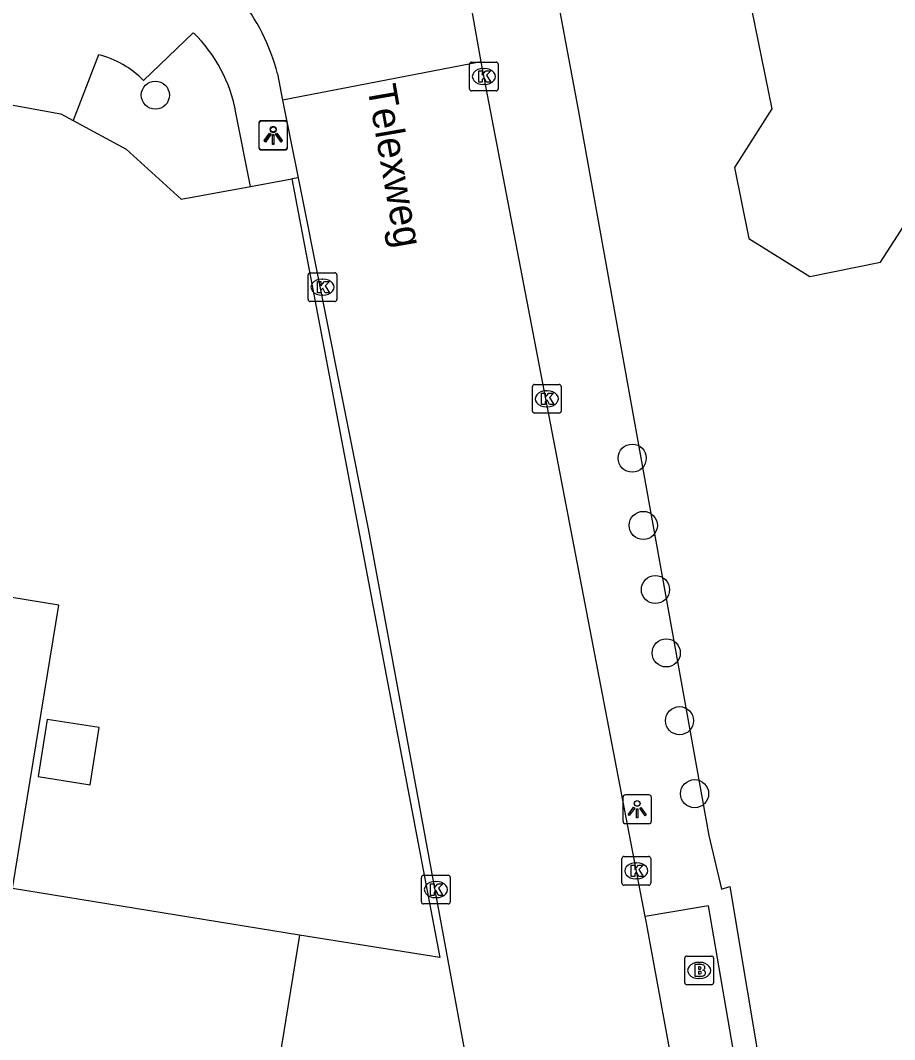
# Model space of a CAD drawing. Extents: x 162990 to 165007, y 383433 to 384336.
# Drawn here: x 163392.98 to 163423.35, y 383982.25 to 384017.67 of the extents above; entities that cross this region are included whole.
import ezdxf

# ---------------------------------------------------------------- set-up
doc = ezdxf.new("R2010")
doc.units = 0
for name, color, linetype in [('IMGEO_Boom', 7, 'Continuous'), ('IMGEO_Brandkraan', 7, 'Continuous'), ('IMGEO_Groenvoorziening', 7, 'Continuous'), ('IMGEO_Hek', 7, 'Continuous'), ('IMGEO_Kolk', 7, 'Continuous'), ('IMGEO_Lage_trafo', 7, 'Continuous'), ('IMGEO_Lichtpunt', 7, 'Continuous'), ('IMGEO_Openbare_ruimte_label', 7, 'Continuous'), ('IMGEO_Pand', 7, 'Continuous'), ('IMGEO_Rijbaan_lokaal_open', 7, 'Continuous'), ('IMGEO_Voetpad_open', 7, 'Continuous')]:
    doc.layers.add(name, color=color, linetype=linetype)

msp = doc.modelspace()

# ---------------------------------------------------------------- linework, layer by layer
at = {"layer": 'IMGEO_Boom'}
for centre in [(163397.667, 384015.068), (163414.235, 384002.456), (163414.62, 384000.118), (163415.043, 383997.891), (163415.418, 383995.69), (163415.879, 383993.335), (163416.403, 383990.798)]:
    msp.add_circle(centre, 0.489, dxfattribs=at)
at = {"layer": 'IMGEO_Brandkraan'}
for p, q in [((163416.137, 383985.158), (163416.989, 383985.158)), ((163416.062, 383984.232), (163416.062, 383985.084)), ((163416.55, 383984.938), (163416.575, 383984.938)), ((163417.063, 383985.084), (163417.063, 383984.232)), ((163416.989, 383984.158), (163416.137, 383984.158)), ((163416.573, 383984.378), (163416.548, 383984.378))]:
    msp.add_line(p, q, dxfattribs=at)
for points in [[(163416.137, 383985.158), (163416.989, 383985.158)], [(163416.062, 383984.232), (163416.062, 383985.084)], [(163416.41, 383984.858), (163416.41, 383984.458), (163416.623, 383984.458)], [(163416.641, 383984.858), (163416.41, 383984.858)], [(163416.589, 383984.777), (163416.535, 383984.777), (163416.535, 383984.701)], [(163417.063, 383985.084), (163417.063, 383984.232)], [(163416.535, 383984.701), (163416.588, 383984.701)], [(163416.597, 383984.625), (163416.535, 383984.625), (163416.535, 383984.544)], [(163416.535, 383984.544), (163416.597, 383984.544)], [(163416.989, 383984.158), (163416.137, 383984.158)]]:
    msp.add_lwpolyline(points, dxfattribs=at)
for centre, radius, start, end in [((163416.139, 383985.082), 0.0765, 91.552, 178.448), ((163416.139, 383985.082), 0.0765, 91.552, 178.448), ((163416.987, 383985.082), 0.0765, 1.552, 88.448), ((163416.987, 383985.082), 0.0765, 1.552, 88.448), ((163416.59, 383984.739), 0.0379, 267.8285, 90.9355), ((163416.645, 383984.713), 0.145, 59.4692, 91.5367), ((163416.67, 383984.76), 0.0922, 285.5137, 58.1501), ((163416.598, 383984.584), 0.0404, 269.8759, 90.5077), ((163416.629, 383984.709), 0.251, 268.6676, 293.5347), ((163416.675, 383984.568), 0.105, 301.3115, 78.989), ((163416.139, 383984.234), 0.0765, 181.552, 268.448), ((163416.139, 383984.234), 0.0765, 181.552, 268.448), ((163416.987, 383984.234), 0.0765, 271.552, 358.448), ((163416.987, 383984.234), 0.0765, 271.552, 358.448)]:
    msp.add_arc(centre, radius, start, end, dxfattribs=at)
for centre, major_axis, ratio, start_param, end_param in [((163416.549, 383984.658), (-0.387, 0.002), 0.722429, 4.712389, 7.853982), ((163416.574, 383984.658), (-0.39, 0.002), 0.717154, 1.570796, 4.712389)]:
    msp.add_ellipse(centre, major_axis=major_axis, ratio=ratio, start_param=start_param, end_param=end_param, dxfattribs=at)
at = {"layer": 'IMGEO_Groenvoorziening'}
msp.add_lwpolyline([(163394.812, 384014.184), (163396.652, 384013.186), (163398.562, 384011.459), (163400.972, 384011.896)], dxfattribs=at)
at = {"layer": 'IMGEO_Hek'}
for points in [[(163359.977, 384000.25), (163372.649, 384005.933), (163381.975, 384010.322), (163389.663, 384014.151), (163392.136, 384014.826), (163394.378, 384014.419), (163394.812, 384014.184)], [(163394.812, 384014.184), (163396.652, 384013.186), (163398.562, 384011.459), (163400.972, 384011.896)], [(163400.972, 384011.896), (163402.405, 384012.156)], [(163402.405, 384012.156), (163407.549, 383985.103), (163402.681, 383985.882)], [(163417.627, 383987.578), (163420.06, 383973.028)]]:
    msp.add_lwpolyline(points, dxfattribs=at)
at = {"layer": 'IMGEO_Kolk'}
for p, q in [((163408.58, 384015.29), (163408.58, 384016.142)), ((163408.655, 384016.216), (163409.507, 384016.216)), ((163409.068, 384015.996), (163409.093, 384015.996)), ((163409.581, 384016.142), (163409.581, 384015.29)), ((163409.507, 384015.216), (163408.655, 384015.216)), ((163409.091, 384015.436), (163409.066, 384015.436)), ((163403.05, 384008.896), (163403.902, 384008.896)), ((163402.975, 384007.97), (163402.975, 384008.822)), ((163403.463, 384008.676), (163403.488, 384008.676)), ((163403.976, 384008.822), (163403.976, 384007.97)), ((163403.902, 384007.896), (163403.05, 384007.896)), ((163403.486, 384008.116), (163403.461, 384008.116)), ((163410.768, 384004.093), (163410.768, 384004.945)), ((163410.843, 384005.019), (163411.695, 384005.019)), ((163411.769, 384004.945), (163411.769, 384004.093)), ((163411.256, 384004.799), (163411.281, 384004.799)), ((163411.279, 384004.239), (163411.254, 384004.239)), ((163411.695, 384004.019), (163410.843, 384004.019)), ((163413.877, 383987.693), (163413.877, 383988.545)), ((163413.952, 383988.619), (163414.804, 383988.619)), ((163414.365, 383988.399), (163414.39, 383988.399)), ((163414.878, 383988.545), (163414.878, 383987.693)), ((163406.987, 383987.966), (163407.839, 383987.966)), ((163406.912, 383987.04), (163406.912, 383987.892)), ((163407.4, 383987.746), (163407.425, 383987.746)), ((163407.913, 383987.892), (163407.913, 383987.04)), ((163414.804, 383987.619), (163413.952, 383987.619)), ((163414.388, 383987.839), (163414.363, 383987.839)), ((163407.839, 383986.966), (163406.987, 383986.966)), ((163407.423, 383987.186), (163407.398, 383987.186))]:
    msp.add_line(p, q, dxfattribs=at)
for points in [[(163408.58, 384015.29), (163408.58, 384016.142)], [(163408.655, 384016.216), (163409.507, 384016.216)], [(163409.581, 384016.142), (163409.581, 384015.29)], [(163408.901, 384015.916), (163409.024, 384015.916), (163409.024, 384015.765), (163409.154, 384015.916), (163409.318, 384015.916), (163409.172, 384015.765), (163409.325, 384015.516), (163409.173, 384015.516), (163409.088, 384015.68), (163409.024, 384015.613), (163409.024, 384015.516), (163408.901, 384015.516), (163408.901, 384015.916)], [(163409.507, 384015.216), (163408.655, 384015.216)], [(163403.05, 384008.896), (163403.902, 384008.896)], [(163402.975, 384007.97), (163402.975, 384008.822)], [(163403.296, 384008.596), (163403.419, 384008.596), (163403.419, 384008.445), (163403.549, 384008.596), (163403.713, 384008.596), (163403.567, 384008.445), (163403.72, 384008.196), (163403.568, 384008.196), (163403.483, 384008.36), (163403.419, 384008.293), (163403.419, 384008.196), (163403.296, 384008.196), (163403.296, 384008.596)], [(163403.976, 384008.822), (163403.976, 384007.97)], [(163403.902, 384007.896), (163403.05, 384007.896)], [(163410.768, 384004.093), (163410.768, 384004.945)], [(163410.843, 384005.019), (163411.695, 384005.019)], [(163411.769, 384004.945), (163411.769, 384004.093)], [(163411.089, 384004.719), (163411.212, 384004.719), (163411.212, 384004.568), (163411.342, 384004.719), (163411.506, 384004.719), (163411.36, 384004.568), (163411.513, 384004.319), (163411.361, 384004.319), (163411.276, 384004.483), (163411.212, 384004.416), (163411.212, 384004.319), (163411.089, 384004.319), (163411.089, 384004.719)], [(163411.695, 384004.019), (163410.843, 384004.019)], [(163413.877, 383987.693), (163413.877, 383988.545)], [(163413.952, 383988.619), (163414.804, 383988.619)], [(163414.198, 383988.319), (163414.321, 383988.319), (163414.321, 383988.168), (163414.451, 383988.319), (163414.615, 383988.319), (163414.469, 383988.168), (163414.622, 383987.919), (163414.47, 383987.919), (163414.385, 383988.083), (163414.321, 383988.016), (163414.321, 383987.919), (163414.198, 383987.919), (163414.198, 383988.319)], [(163414.878, 383988.545), (163414.878, 383987.693)], [(163406.987, 383987.966), (163407.839, 383987.966)], [(163406.912, 383987.04), (163406.912, 383987.892)], [(163407.233, 383987.666), (163407.356, 383987.666), (163407.356, 383987.515), (163407.486, 383987.666), (163407.65, 383987.666), (163407.504, 383987.515), (163407.657, 383987.266), (163407.505, 383987.266), (163407.42, 383987.43), (163407.356, 383987.363), (163407.356, 383987.266), (163407.233, 383987.266), (163407.233, 383987.666)], [(163407.913, 383987.892), (163407.913, 383987.04)], [(163414.804, 383987.619), (163413.952, 383987.619)], [(163407.839, 383986.966), (163406.987, 383986.966)]]:
    msp.add_lwpolyline(points, dxfattribs=at)
for centre, start, end in [((163408.657, 384016.14), 91.552, 178.448), ((163408.657, 384016.14), 91.552, 178.448), ((163409.505, 384016.14), 1.552, 88.448), ((163409.505, 384016.14), 1.552, 88.448), ((163408.657, 384015.292), 181.552, 268.448), ((163408.657, 384015.292), 181.552, 268.448), ((163409.505, 384015.292), 271.552, 358.448), ((163409.505, 384015.292), 271.552, 358.448), ((163403.052, 384008.82), 91.552, 178.448), ((163403.052, 384008.82), 91.552, 178.448), ((163403.9, 384008.82), 1.552, 88.448), ((163403.9, 384008.82), 1.552, 88.448), ((163403.052, 384007.972), 181.552, 268.448), ((163403.052, 384007.972), 181.552, 268.448), ((163403.9, 384007.972), 271.552, 358.448), ((163403.9, 384007.972), 271.552, 358.448), ((163410.845, 384004.943), 91.552, 178.448), ((163410.845, 384004.943), 91.552, 178.448), ((163411.693, 384004.943), 1.552, 88.448), ((163411.693, 384004.943), 1.552, 88.448), ((163410.845, 384004.095), 181.552, 268.448), ((163410.845, 384004.095), 181.552, 268.448), ((163411.693, 384004.095), 271.552, 358.448), ((163411.693, 384004.095), 271.552, 358.448), ((163413.954, 383988.543), 91.552, 178.448), ((163413.954, 383988.543), 91.552, 178.448), ((163414.802, 383988.543), 1.552, 88.448), ((163414.802, 383988.543), 1.552, 88.448), ((163406.989, 383987.89), 91.552, 178.448), ((163406.989, 383987.89), 91.552, 178.448), ((163407.837, 383987.89), 1.552, 88.448), ((163407.837, 383987.89), 1.552, 88.448), ((163413.954, 383987.695), 181.552, 268.448), ((163413.954, 383987.695), 181.552, 268.448), ((163414.802, 383987.695), 271.552, 358.448), ((163414.802, 383987.695), 271.552, 358.448), ((163406.989, 383987.042), 181.552, 268.448), ((163406.989, 383987.042), 181.552, 268.448), ((163407.837, 383987.042), 271.552, 358.448), ((163407.837, 383987.042), 271.552, 358.448)]:
    msp.add_arc(centre, 0.0765, start, end, dxfattribs=at)
for centre, major_axis, ratio, start_param, end_param in [((163409.067, 384015.716), (-0.387, 0.002), 0.722429, 4.712389, 7.853982), ((163409.092, 384015.716), (-0.39, 0.002), 0.717154, 1.570796, 4.712389), ((163403.462, 384008.396), (-0.387, 0.002), 0.722429, 4.712389, 7.853982), ((163403.487, 384008.396), (-0.39, 0.002), 0.717154, 1.570796, 4.712389), ((163411.255, 384004.519), (-0.387, 0.002), 0.722429, 4.712389, 7.853982), ((163411.28, 384004.519), (-0.39, 0.002), 0.717154, 1.570796, 4.712389), ((163414.364, 383988.119), (-0.387, 0.002), 0.722429, 4.712389, 7.853982), ((163414.389, 383988.119), (-0.39, 0.002), 0.717154, 1.570796, 4.712389), ((163407.399, 383987.466), (-0.387, 0.002), 0.722429, 4.712389, 7.853982), ((163407.424, 383987.466), (-0.39, 0.002), 0.717154, 1.570796, 4.712389)]:
    msp.add_ellipse(centre, major_axis=major_axis, ratio=ratio, start_param=start_param, end_param=end_param, dxfattribs=at)
at = {"layer": 'IMGEO_Lage_trafo'}
msp.add_lwpolyline([(163395.405, 383991.109), (163395.714, 383993.093), (163393.908, 383993.374), (163393.599, 383991.391), (163395.405, 383991.109)], dxfattribs=at)
at = {"layer": 'IMGEO_Lichtpunt'}
for p, q in [((163402.163, 384014.181), (163401.355, 384014.181)), ((163402.163, 384014.181), (163401.355, 384014.181)), ((163402.166, 384014.16), (163401.358, 384014.16)), ((163402.166, 384014.16), (163401.358, 384014.16)), ((163401.261, 384014.086), (163401.261, 384013.279)), ((163401.261, 384014.086), (163401.261, 384013.279)), ((163401.264, 384014.065), (163401.264, 384013.258)), ((163401.264, 384014.065), (163401.264, 384013.258)), ((163402.257, 384013.279), (163402.257, 384014.086)), ((163402.257, 384013.279), (163402.257, 384014.086)), ((163402.26, 384013.258), (163402.26, 384014.065)), ((163402.26, 384013.258), (163402.26, 384014.065)), ((163401.355, 384013.185), (163402.163, 384013.185)), ((163401.355, 384013.185), (163402.163, 384013.185)), ((163401.358, 384013.164), (163402.166, 384013.164)), ((163401.358, 384013.164), (163402.166, 384013.164)), ((163413.91, 383990.661), (163413.91, 383989.854)), ((163413.91, 383990.661), (163413.91, 383989.854)), ((163414.812, 383990.756), (163414.004, 383990.756)), ((163414.812, 383990.756), (163414.004, 383990.756)), ((163414.906, 383989.854), (163414.906, 383990.661)), ((163414.906, 383989.854), (163414.906, 383990.661)), ((163414.004, 383989.76), (163414.812, 383989.76)), ((163414.004, 383989.76), (163414.812, 383989.76))]:
    msp.add_line(p, q, dxfattribs=at)
for points in [[(163401.635, 384013.75), (163401.674, 384013.722), (163401.486, 384013.46), (163401.448, 384013.487), (163401.635, 384013.75)], [(163401.638, 384013.729), (163401.677, 384013.701), (163401.489, 384013.439), (163401.451, 384013.466), (163401.638, 384013.729)], [(163401.737, 384013.702), (163401.784, 384013.702), (163401.784, 384013.38), (163401.737, 384013.38), (163401.737, 384013.702)], [(163401.74, 384013.681), (163401.787, 384013.681), (163401.787, 384013.359), (163401.74, 384013.359), (163401.74, 384013.681)], [(163401.847, 384013.722), (163401.885, 384013.749), (163402.072, 384013.487), (163402.033, 384013.459), (163401.847, 384013.722)], [(163401.85, 384013.701), (163401.888, 384013.728), (163402.075, 384013.466), (163402.036, 384013.438), (163401.85, 384013.701)], [(163414.284, 383990.325), (163414.323, 383990.297), (163414.135, 383990.035), (163414.097, 383990.062), (163414.284, 383990.325)], [(163414.386, 383990.277), (163414.433, 383990.277), (163414.433, 383989.955), (163414.386, 383989.955), (163414.386, 383990.277)], [(163414.496, 383990.297), (163414.534, 383990.324), (163414.721, 383990.062), (163414.682, 383990.034), (163414.496, 383990.297)]]:
    msp.add_lwpolyline(points, dxfattribs=at)
for centre in [(163401.76, 384013.884), (163401.763, 384013.863), (163414.409, 383990.459)]:
    msp.add_circle(centre, 0.0994, dxfattribs=at)
for centre, start, end in [((163401.355, 384014.086), 90, 180), ((163401.355, 384014.086), 90, 180), ((163401.358, 384014.065), 90, 180), ((163401.358, 384014.065), 90, 180), ((163402.163, 384014.086), 0, 90), ((163402.163, 384014.086), 0, 90), ((163402.166, 384014.065), 0, 90), ((163402.166, 384014.065), 0, 90), ((163401.355, 384013.279), 180, 270), ((163401.355, 384013.279), 180, 270), ((163401.358, 384013.258), 180, 270), ((163401.358, 384013.258), 180, 270), ((163402.163, 384013.279), 270, 0), ((163402.163, 384013.279), 270, 360), ((163402.166, 384013.258), 270, 0), ((163402.166, 384013.258), 270, 360), ((163414.004, 383990.661), 90, 180), ((163414.004, 383990.661), 90, 180), ((163414.812, 383990.661), 0, 90), ((163414.812, 383990.661), 0, 90), ((163414.004, 383989.854), 180, 270), ((163414.004, 383989.854), 180, 270), ((163414.812, 383989.854), 270, 0), ((163414.812, 383989.854), 270, 360)]:
    msp.add_arc(centre, 0.0946, start, end, dxfattribs=at)
at = {"layer": 'IMGEO_Pand'}
for points in [[(163425.491, 384026.173), (163417.089, 384024.469), (163417.219, 384023.83), (163415.735, 384023.529), (163416.336, 384020.565), (163417.807, 384020.864), (163417.899, 384020.414), (163417.36, 384020.305), (163417.595, 384019.149), (163418.135, 384019.259), (163419.081, 384014.594), (163417.785, 384012.56), (163418.286, 384010.091), (163420.402, 384008.765), (163422.862, 384009.265), (163424.119, 384011.224)], [(163402.681, 383985.882), (163392.709, 383987.505), (163392.906, 383988.71), (163393.32, 383991.253), (163394.313, 383997.352), (163379.538, 383999.758), (163378.543, 383993.649), (163378.125, 383991.08), (163377.924, 383989.849), (163358.252, 383993.053), (163356.439, 383981.918), (163352.002, 383982.641), (163351.607, 383980.215), (163351.702, 383980.199), (163356.032, 383979.494), (163355.647, 383977.127), (163355.028, 383973.33), (163399.459, 383966.094)], [(163402.681, 383985.882), (163399.459, 383966.094)]]:
    msp.add_lwpolyline(points, dxfattribs=at)
at = {"layer": 'IMGEO_Rijbaan_lokaal_open'}
for points in [[(163408.985, 384016.224), (163407.83, 384022.758)], [(163408.985, 384016.224), (163402.087, 384014.898)], [(163414.685, 383986.526), (163408.985, 384016.224)], [(163401.911, 384015.809), (163402.087, 384014.898)], [(163402.087, 384014.898), (163402.626, 384012.196)], [(163402.626, 384012.196), (163405.058, 384000), (163411.655, 383964.3)], [(163416.961, 383974.175), (163414.715, 383986.371), (163414.685, 383986.526)]]:
    msp.add_lwpolyline(points, dxfattribs=at)
msp.add_arc((163395.107, 384014.076), 7.021, 14.2868, 113.0639, dxfattribs=at)
at = {"layer": 'IMGEO_Voetpad_open'}
for points in [[(163410.036, 384026.962), (163412.357, 384014.563), (163416.896, 383989.35), (163417.337, 383987.477), (163417.627, 383987.578), (163420.06, 383973.028)], [(163398.987, 384017.233), (163397.258, 384015.578)], [(163395.692, 384016.472), (163394.812, 384014.184)], [(163359.977, 384000.25), (163372.649, 384005.933), (163381.975, 384010.322), (163389.663, 384014.151), (163392.136, 384014.826), (163394.378, 384014.419), (163394.812, 384014.184)], [(163400.972, 384011.896), (163400.465, 384014.459)], [(163400.972, 384011.896), (163402.405, 384012.156)], [(163402.626, 384012.196), (163402.405, 384012.156)], [(163402.405, 384012.156), (163407.549, 383985.103), (163402.681, 383985.882)], [(163419.228, 383973.306), (163416.881, 383986.9), (163416.534, 383986.841), (163414.685, 383986.526)]]:
    msp.add_lwpolyline(points, dxfattribs=at)
for centre, radius, start, end in [((163395.486, 384013.587), 5.055, 9.9341, 46.1637), ((163394.881, 384013.233), 3.339, 44.6126, 75.9449)]:
    msp.add_arc(centre, radius, start, end, dxfattribs=at)

# ---------------------------------------------------------------- texts
at = {"layer": 'IMGEO_Openbare_ruimte_label'}
msp.add_text('Telexweg', height=1, rotation=279.9051, dxfattribs=at).set_placement((163405.025, 384015.355))

doc.saveas('drawing.dxf')
